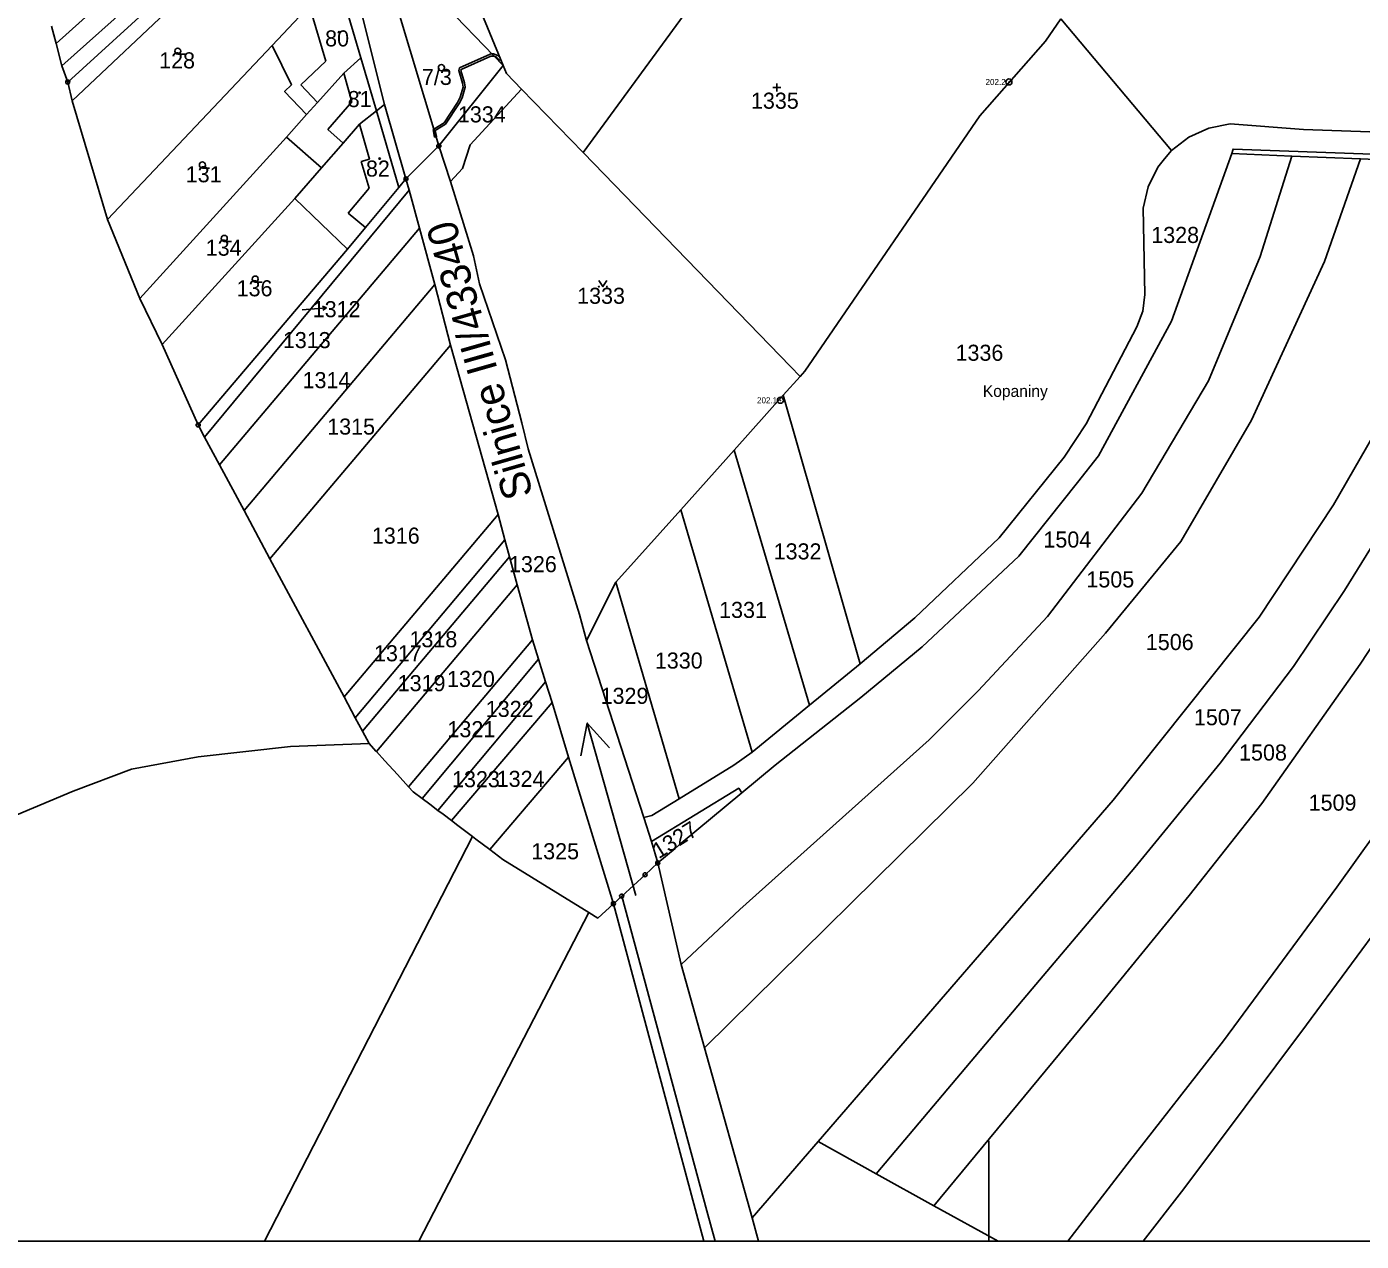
# Model space of a CAD drawing. Extents: x -564516 to -563466, y -1163913 to -1163170.
# Drawn here: x -564230.8 to -563898.7, y -1163912.5 to -1163610.3 of the extents above; entities that cross this region are included whole.
import ezdxf

# ---------------------------------------------------------------- set-up
doc = ezdxf.new("R2010")
doc.units = 0
for name, color, linetype in [('_parcely', 7, 'Continuous'), ('_parcely přehledka', 7, 'Continuous'), ('_ZOV', 7, 'Continuous'), ('Hranice parcel', 7, 'Continuous'), ('Obvod PU', 7, 'Continuous'), ('Parcelní čísla', 7, 'Continuous'), ('Pop  PČ popisy', 7, 'Continuous'), ('Vnitřní kresba', 7, 'Continuous'), ('Věcná břemena k části', 7, 'Continuous'), ('Značky bodu BP', 7, 'Continuous'), ('Značky budov', 7, 'Continuous'), ('Značky kultur', 7, 'Continuous')]:
    doc.layers.add(name, color=color, linetype=linetype)

msp = doc.modelspace()

# ---------------------------------------------------------------- linework, layer by layer
at = {"layer": '_parcely'}
msp.add_line((-563991.35, -1163912.53), (-563991.35, -1163887.53), dxfattribs=at)
at = {"layer": '_parcely přehledka'}
msp.add_lwpolyline([(-564516.35, -1163170.03), (-564516.35, -1163912.53), (-563466.35, -1163912.53), (-563466.35, -1163170.03)], dxfattribs=at)
at = {"layer": '_ZOV'}
msp.add_line((-564079.2, -1163826.53), (-564091.29, -1163783.59), dxfattribs=at)
msp.add_lwpolyline([(-564092.86, -1163791.75), (-564091.29, -1163783.59), (-564085.7, -1163789.74)], dxfattribs=at)
at = {"layer": 'Hranice parcel'}
for p, q in [((-564223.46, -1163614.55), (-564168.46, -1163564.89)), ((-564222.05, -1163620.11), (-564164.82, -1163568.62)), ((-564220.56, -1163624.11), (-564162.36, -1163571.14)), ((-564219.45, -1163628.81), (-564176.54, -1163588.25)), ((-564141.45, -1163589.58), (-564112.22, -1163619.96)), ((-564147.6, -1163618.07), (-564153.46, -1163598.26)), ((-564092.3, -1163641.63), (-564063.05, -1163601.67)), ((-564224.59, -1163610.2), (-564223.46, -1163614.55)), ((-564162.89, -1163607.78), (-564169.68, -1163615)), ((-563945.88, -1163641.11), (-563973.39, -1163608.38)), ((-564223.46, -1163614.55), (-564222.05, -1163620.11)), ((-564210.67, -1163658.27), (-564169.68, -1163615)), ((-564222.05, -1163620.11), (-564220.56, -1163624.11)), ((-564143.7, -1163631.27), (-564147.6, -1163618.07)), ((-564128.21, -1163640.02), (-564112.22, -1163619.96)), ((-564220.56, -1163624.11), (-564219.45, -1163628.81)), ((-564107.61, -1163625.85), (-564092.3, -1163641.63)), ((-564219.45, -1163628.81), (-564210.67, -1163658.27)), ((-564141.75, -1163629.73), (-564143.7, -1163631.27)), ((-564136.4, -1163648.2), (-564141.75, -1163629.73)), ((-564161.12, -1163632.21), (-564166.15, -1163637.81)), ((-564202.62, -1163678), (-564166.15, -1163637.81)), ((-564166.15, -1163637.81), (-564157.42, -1163645.45)), ((-564136.4, -1163648.2), (-564128.21, -1163640.02)), ((-564128.21, -1163640.02), (-564125.28, -1163648.88)), ((-563915.93, -1163642.54), (-563930.91, -1163641.92)), ((-563898.88, -1163643.25), (-563915.93, -1163642.54)), ((-563866.43, -1163644.59), (-563898.88, -1163643.25)), ((-564157.42, -1163645.45), (-564164.08, -1163653.05)), ((-564135.56, -1163651.03), (-564136.4, -1163648.2)), ((-564197.05, -1163689.43), (-564164.08, -1163653.05)), ((-564186.49, -1163712.43), (-564135.56, -1163651.03)), ((-564164.08, -1163653.05), (-564150.92, -1163665.7)), ((-564133.04, -1163660.47), (-564135.56, -1163651.03)), ((-564210.67, -1163658.27), (-564202.62, -1163678)), ((-564182.77, -1163719.37), (-564133.04, -1163660.47)), ((-564129.24, -1163674.51), (-564133.04, -1163660.47)), ((-564188.1, -1163709.43), (-564150.92, -1163665.7)), ((-564176.67, -1163730.73), (-564129.24, -1163674.51)), ((-564125.31, -1163689.57), (-564129.24, -1163674.51)), ((-564202.62, -1163678), (-564197.05, -1163689.43)), ((-564197.05, -1163689.43), (-564188.1, -1163709.43)), ((-564170.24, -1163742.74), (-564125.31, -1163689.57)), ((-564113.48, -1163731.73), (-564125.31, -1163689.57)), ((-564042.49, -1163702.03), (-564038.32, -1163697.37)), ((-564054.69, -1163715.66), (-564042.49, -1163702.03)), ((-564023.36, -1163768.85), (-564042.49, -1163702.03)), ((-564188.1, -1163709.43), (-564186.49, -1163712.43)), ((-564186.49, -1163712.43), (-564182.77, -1163719.37)), ((-564068.02, -1163730.56), (-564054.69, -1163715.66)), ((-564054.69, -1163715.66), (-564035.96, -1163779.13)), ((-564182.77, -1163719.37), (-564176.67, -1163730.73)), ((-564176.67, -1163730.73), (-564170.24, -1163742.74)), ((-564151.79, -1163777.11), (-564113.48, -1163731.73)), ((-564111.75, -1163738.01), (-564113.48, -1163731.73)), ((-564084.13, -1163748.56), (-564068.02, -1163730.56)), ((-564050.26, -1163790.8), (-564068.02, -1163730.56)), ((-564149.04, -1163782.26), (-564111.75, -1163738.01)), ((-564110.59, -1163742.26), (-564111.75, -1163738.01)), ((-564170.24, -1163742.74), (-564151.79, -1163777.11)), ((-564110.59, -1163742.26), (-564147.22, -1163785.64)), ((-564108.68, -1163749.18), (-564110.59, -1163742.26)), ((-564143.75, -1163790.7), (-564108.68, -1163749.18)), ((-564104.87, -1163762.87), (-564108.68, -1163749.18)), ((-564091.46, -1163763.02), (-564084.13, -1163748.56)), ((-564068.41, -1163802.44), (-564084.13, -1163748.56)), ((-564135.73, -1163799.43), (-564104.87, -1163762.87)), ((-564103.38, -1163767.72), (-564104.87, -1163762.87)), ((-564091.46, -1163763.02), (-564077.18, -1163807.12)), ((-564132.34, -1163802.38), (-564103.38, -1163767.72)), ((-564101.66, -1163773.32), (-564103.38, -1163767.72)), ((-564035.96, -1163779.13), (-564023.36, -1163768.85)), ((-564128.43, -1163805.33), (-564101.66, -1163773.32)), ((-564100.04, -1163778.49), (-564101.66, -1163773.32)), ((-564151.79, -1163777.11), (-564149.04, -1163782.26)), ((-564125.08, -1163807.86), (-564100.04, -1163778.49)), ((-564095.92, -1163792.07), (-564100.04, -1163778.49)), ((-564050.26, -1163790.8), (-564035.96, -1163779.13)), ((-564149.04, -1163782.26), (-564147.22, -1163785.64)), ((-564147.22, -1163785.64), (-564145.57, -1163788.72)), ((-564115.55, -1163815.06), (-564095.92, -1163792.07)), ((-564084.77, -1163828.54), (-564095.92, -1163792.07)), ((-564077.18, -1163807.12), (-564075.32, -1163813.06)), ((-564075.32, -1163813.06), (-564073.75, -1163818.41)), ((-564067.92, -1163843.63), (-564073.75, -1163818.41)), ((-564062.09, -1163864.39), (-564067.92, -1163843.63)), ((-564050.26, -1163906.68), (-564062.09, -1163864.39)), ((-564050.26, -1163906.68), (-564033.85, -1163887.71)), ((-564033.85, -1163887.71), (-564019.41, -1163895.71)), ((-564019.41, -1163895.71), (-564005.03, -1163903.67)), ((-564005.03, -1163903.67), (-563989.02, -1163912.53))]:
    msp.add_line(p, q, dxfattribs=at)
for points in [[(-564141.75, -1163629.73), (-564147.11, -1163608.19), (-564150.44, -1163590.7), (-564149.91, -1163571.99), (-564143.77, -1163544.97)], [(-564112.22, -1163619.96), (-564129.19, -1163578.66), (-564125.43, -1163565.71)], [(-564141.45, -1163589.58), (-564138.93, -1163604.36), (-564128.21, -1163640.02)], [(-564038.32, -1163697.37), (-564037.15, -1163696.07), (-563993.61, -1163632.54), (-563977.25, -1163613.92), (-563973.39, -1163608.38)], [(-564169.68, -1163615), (-564164.9, -1163624.84), (-564166.58, -1163626.42), (-564161.12, -1163632.21)], [(-564161.12, -1163632.21), (-564158.44, -1163629.22), (-564151.87, -1163621.91), (-564147.6, -1163618.07)], [(-564112.22, -1163619.96), (-564111.4, -1163621.95), (-564107.61, -1163625.85)], [(-564125.28, -1163648.88), (-564122.35, -1163645.58), (-564120.45, -1163639.74), (-564107.61, -1163625.85)], [(-564157.42, -1163645.45), (-564152.02, -1163639.28), (-564147.94, -1163634.62), (-564143.7, -1163631.27)], [(-563945.88, -1163641.11), (-563941.57, -1163637.81), (-563936.63, -1163635.58), (-563931.3, -1163634.54), (-563913.06, -1163635.92), (-563861.14, -1163637.78)], [(-564092.3, -1163641.63), (-564040.72, -1163694.91), (-564038.32, -1163697.37)], [(-564067.92, -1163843.63), (-564053.32, -1163830), (-564006.23, -1163787.74), (-563993.99, -1163775.6), (-563976.74, -1163757.12), (-563953.25, -1163726.38), (-563936.65, -1163698.43), (-563923.86, -1163667.53), (-563915.93, -1163642.54)], [(-564062.09, -1163864.39), (-563995.33, -1163798.54), (-563962.27, -1163761.24), (-563943.57, -1163738.41), (-563925.96, -1163708.23), (-563907.83, -1163668.76), (-563898.88, -1163643.25)], [(-564023.36, -1163768.85), (-564009.73, -1163757.43), (-563988.8, -1163737.54), (-563972.63, -1163717.42), (-563967.15, -1163709.12), (-563954.55, -1163685.04), (-563953.03, -1163681.15), (-563952.52, -1163676.96), (-563952.92, -1163655.47), (-563951.71, -1163650.18), (-563949.32, -1163645.31), (-563947.61, -1163643.22), (-563945.88, -1163641.11)], [(-564033.85, -1163887.71), (-563960.37, -1163802.77), (-563924.09, -1163757.23), (-563905.61, -1163729.28), (-563893.92, -1163709.01), (-563880, -1163679.45), (-563866.43, -1163644.59)], [(-564019.41, -1163895.71), (-563980.6, -1163849.7), (-563954.99, -1163819.51), (-563933.77, -1163793.6), (-563915.51, -1163769.54), (-563902.82, -1163750.6), (-563880.21, -1163714.08), (-563865.64, -1163681.81), (-563852.28, -1163645.65)], [(-564005.03, -1163903.67), (-563965.09, -1163855.39), (-563941.49, -1163826.5), (-563923.42, -1163803.62), (-563898.92, -1163768.98), (-563879.88, -1163739.93), (-563867.29, -1163716.65), (-563853.12, -1163688.16), (-563837.56, -1163646.83)], [(-564150.92, -1163665.7), (-564146.44, -1163660.3), (-564138.18, -1163650.34), (-564136.4, -1163648.2)], [(-564125.28, -1163648.88), (-564119.58, -1163667.35), (-564118.1, -1163674.3), (-564111.58, -1163693.21), (-564107.59, -1163708.92), (-564105.94, -1163715.39), (-564093.18, -1163756.62), (-564091.46, -1163763.02)], [(-563971.69, -1163912.53), (-563956.92, -1163893.35), (-563932.93, -1163862.62), (-563904.78, -1163824.4), (-563885.89, -1163798.15), (-563869.34, -1163772.9), (-563860.8, -1163759.16), (-563843.13, -1163727.45), (-563830.48, -1163702.96), (-563823.28, -1163687.14), (-563818.58, -1163675.31), (-563810.46, -1163651.3)], [(-563952.94, -1163912.53), (-563942.84, -1163899.5), (-563912.32, -1163858.67), (-563872.16, -1163804.24), (-563858.94, -1163783.59), (-563847.66, -1163765.02), (-563838.38, -1163748.17), (-563818.3, -1163711.53), (-563805.22, -1163681.25), (-563795.8, -1163653.08)], [(-564068.41, -1163802.44), (-564054.76, -1163794.08), (-564050.26, -1163790.8)], [(-564052.83, -1163800.98), (-564053.56, -1163799.83), (-564075.32, -1163813.06)], [(-564077.18, -1163807.12), (-564075.21, -1163806.57), (-564068.41, -1163802.44)], [(-564171.55, -1163912.53), (-564119.83, -1163811.83)], [(-564084.77, -1163828.54), (-564064.12, -1163905.73), (-564062.23, -1163912.53)], [(-564082.71, -1163826.65), (-564061.52, -1163904.92), (-564059.43, -1163912.53)], [(-564090.91, -1163830.72), (-564133.16, -1163912.53)], [(-564048.67, -1163912.53), (-564050.26, -1163906.68)]]:
    msp.add_lwpolyline(points, dxfattribs=at)
at = {"layer": 'Obvod PU'}
msp.add_line((-564082.71, -1163826.65), (-564084.77, -1163828.54), dxfattribs=at)
msp.add_line((-564082.71, -1163826.65), (-564084.77, -1163828.54), dxfattribs=at)
for points in [[(-563930.91, -1163641.92), (-563945.92, -1163683.61), (-563964.08, -1163717.1), (-563969.31, -1163723.74), (-563983.9, -1163742.07), (-564007.92, -1163764.64), (-564023.16, -1163777.23), (-564044.53, -1163794.09), (-564052.83, -1163800.98)], [(-563930.91, -1163641.92), (-563945.92, -1163683.61), (-563964.08, -1163717.1), (-563969.31, -1163723.74), (-563983.9, -1163742.07), (-564007.92, -1163764.64), (-564023.16, -1163777.23), (-564044.53, -1163794.09), (-564052.83, -1163800.98)], [(-563863.67, -1163643.2), (-563930.57, -1163640.78), (-563930.91, -1163641.92)], [(-563863.67, -1163643.2), (-563930.57, -1163640.78), (-563930.91, -1163641.92)], [(-564145.57, -1163788.72), (-564165.13, -1163789.46), (-564188.06, -1163792), (-564204.66, -1163795.09), (-564219.21, -1163800.53), (-564275.9, -1163824.32), (-564309.77, -1163843.83), (-564359.7, -1163877.05), (-564371.94, -1163888.45), (-564374.47, -1163874.66), (-564375.88, -1163841.01), (-564379.57, -1163838.23)], [(-564145.57, -1163788.72), (-564165.13, -1163789.46), (-564188.06, -1163792), (-564204.66, -1163795.09), (-564219.21, -1163800.53), (-564275.9, -1163824.32), (-564309.77, -1163843.83), (-564359.7, -1163877.05), (-564371.94, -1163888.45), (-564374.47, -1163874.66), (-564375.88, -1163841.01), (-564379.57, -1163838.23)], [(-564143.75, -1163790.7), (-564143.87, -1163790.57), (-564145.57, -1163788.72)], [(-564143.75, -1163790.7), (-564143.87, -1163790.57), (-564145.57, -1163788.72)], [(-564135.73, -1163799.43), (-564138.49, -1163796.43), (-564141.64, -1163793), (-564143.75, -1163790.7)], [(-564135.73, -1163799.43), (-564138.49, -1163796.43), (-564141.64, -1163793), (-564143.75, -1163790.7)], [(-564132.34, -1163802.38), (-564134.59, -1163800.68), (-564135.73, -1163799.43)], [(-564132.34, -1163802.38), (-564134.59, -1163800.68), (-564135.73, -1163799.43)], [(-564128.43, -1163805.33), (-564130.46, -1163803.8), (-564132.34, -1163802.38)], [(-564128.43, -1163805.33), (-564130.46, -1163803.8), (-564132.34, -1163802.38)], [(-564052.83, -1163800.98), (-564067.88, -1163813.47), (-564069.41, -1163814.81), (-564073.75, -1163818.41)], [(-564052.83, -1163800.98), (-564067.88, -1163813.47), (-564069.41, -1163814.81), (-564073.75, -1163818.41)], [(-564125.08, -1163807.86), (-564127.17, -1163806.28), (-564128.43, -1163805.33)], [(-564125.08, -1163807.86), (-564127.17, -1163806.28), (-564128.43, -1163805.33)], [(-564119.83, -1163811.83), (-564123.49, -1163809.06), (-564125.08, -1163807.86)], [(-564119.83, -1163811.83), (-564123.49, -1163809.06), (-564125.08, -1163807.86)], [(-564115.55, -1163815.06), (-564119, -1163812.46), (-564119.83, -1163811.83)], [(-564115.55, -1163815.06), (-564119, -1163812.46), (-564119.83, -1163811.83)], [(-564090.91, -1163830.72), (-564112.29, -1163817.52), (-564115.55, -1163815.06)], [(-564090.91, -1163830.72), (-564112.29, -1163817.52), (-564115.55, -1163815.06)], [(-564073.75, -1163818.41), (-564076.9, -1163821.34), (-564082.71, -1163826.65)], [(-564073.75, -1163818.41), (-564076.9, -1163821.34), (-564082.71, -1163826.65)], [(-564084.77, -1163828.54), (-564088.67, -1163832.11), (-564090.91, -1163830.72)], [(-564084.77, -1163828.54), (-564088.67, -1163832.11), (-564090.91, -1163830.72)]]:
    msp.add_lwpolyline(points, dxfattribs=at)
at = {"layer": 'Pop  PČ popisy'}
for p, q in [((-564159.11, -1163680.51), (-564156.12, -1163680.25)), ((-564156.12, -1163680.25), (-564157.16, -1163679.84)), ((-564156.12, -1163680.25), (-564157.07, -1163680.84)), ((-564162.18, -1163680.77), (-564159.11, -1163680.51))]:
    msp.add_line(p, q, dxfattribs=at)
at = {"layer": 'Vnitřní kresba'}
for p, q in [((-564160.37, -1163605.23), (-564156.31, -1163618.94)), ((-564156.31, -1163618.94), (-564162.57, -1163624.84)), ((-564149.84, -1163629.05), (-564151.87, -1163621.91)), ((-564158.44, -1163629.22), (-564162.57, -1163624.84)), ((-564149.84, -1163629.05), (-564155.86, -1163635.92)), ((-564138.18, -1163650.34), (-564143.7, -1163631.27)), ((-564155.86, -1163635.92), (-564152.02, -1163639.28)), ((-564145.43, -1163643.26), (-564147.94, -1163634.62)), ((-564145.43, -1163643.26), (-564147.5, -1163643.86)), ((-564147.5, -1163643.86), (-564145.58, -1163650.49)), ((-564150.75, -1163656.72), (-564145.58, -1163650.49)), ((-564150.75, -1163656.72), (-564146.44, -1163660.3))]:
    msp.add_line(p, q, dxfattribs=at)
at = {"layer": 'Věcná břemena k části'}
msp.add_lwpolyline([(-564129.09, -1163636.18), (-564126.56, -1163634.59), (-564123.17, -1163629.45), (-564122.4, -1163628.02), (-564121.66, -1163625.41), (-564121.8, -1163624.29), (-564122.71, -1163621.24), (-564122.63, -1163620.95), (-564115.3, -1163617.69), (-564114.43, -1163617.66), (-564113.85, -1163617.89), (-564113.13, -1163618.68), (-564112.79, -1163618.58), (-564113.13, -1163617.74), (-564113.27, -1163617.78), (-564113.55, -1163617.47), (-564114.58, -1163617.06), (-564114.95, -1163617.12), (-564115.44, -1163617.21), (-564123.05, -1163620.59), (-564123.23, -1163621.24), (-564122.3, -1163624.39), (-564122.16, -1163625.37), (-564122.86, -1163627.84), (-564123.59, -1163629.19), (-564126.92, -1163634.23), (-564129.47, -1163635.83), (-564129.65, -1163635.94), (-564129.26, -1163637.8), (-564128.9, -1163637.72), (-564128.77, -1163637.69)], close=True, dxfattribs=at)
at = {"layer": 'Značky bodu BP'}
for centre, radius in [((-564220.56, -1163624.11), 0.5), ((-563986.34, -1163624.09), 0.75), ((-564220.56, -1163624.11), 0.0303), ((-563986.34, -1163624.09), 0.03), ((-564128.21, -1163640.02), 0.5), ((-564128.21, -1163640.02), 0.0303), ((-564136.4, -1163648.2), 0.5), ((-564136.4, -1163648.2), 0.0303), ((-564043.21, -1163703.28), 0.75), ((-564043.21, -1163703.28), 0.03), ((-564188.1, -1163709.43), 0.5), ((-564188.1, -1163709.43), 0.0303), ((-564073.75, -1163818.41), 0.5), ((-564073.75, -1163818.41), 0.0303), ((-564076.9, -1163821.34), 0.5), ((-564076.9, -1163821.34), 0.0303), ((-564082.71, -1163826.65), 0.5), ((-564082.71, -1163826.65), 0.0303), ((-564084.77, -1163828.54), 0.5), ((-564084.77, -1163828.54), 0.0303)]:
    msp.add_circle(centre, radius, dxfattribs=at)
at = {"layer": 'Značky budov'}
for centre in [(-564153.05, -1163611.7), (-564147.94, -1163626.79), (-564142.94, -1163643.16)]:
    msp.add_circle(centre, 0.175, dxfattribs=at)
at = {"layer": 'Značky kultur'}
for p, q in [((-564193.17, -1163617.17), (-564191.42, -1163617.17)), ((-564127.56, -1163621.28), (-564125.81, -1163621.28)), ((-564043.13, -1163625.48), (-564045.13, -1163625.48)), ((-564044.13, -1163626.48), (-564044.13, -1163624.48)), ((-564187.04, -1163645.5), (-564185.29, -1163645.5)), ((-564181.59, -1163663.77), (-564179.84, -1163663.77)), ((-564173.9, -1163673.87), (-564172.15, -1163673.87))]:
    msp.add_line(p, q, dxfattribs=at)
msp.add_lwpolyline([(-564088.37, -1163673.51), (-564087.37, -1163675.01), (-564086.37, -1163673.51)], dxfattribs=at)
for centre, radius in [((-564193.17, -1163616.42), 0.75), ((-564127.56, -1163620.53), 0.75), ((-564187.04, -1163644.75), 0.75), ((-564181.59, -1163663.02), 0.75), ((-564173.9, -1163673.12), 0.75), ((-564088.37, -1163675.01), 0.1), ((-564086.37, -1163675.01), 0.1)]:
    msp.add_circle(centre, radius, dxfattribs=at)

# ---------------------------------------------------------------- texts
at = {"layer": '_ZOV'}
msp.add_text('Silnice III/43340', height=7.5, rotation=105.9051, dxfattribs=at).set_placement((-564104.68, -1163726.69))
at = {"layer": 'Parcelní čísla'}
for s, p in [('80', (-564156.5, -1163615.25)), ('128', (-564197.8, -1163620.72)), ('7/3', (-564132.41, -1163624.83)), ('81', (-564150.88, -1163630.34)), ('1335', (-564050.54, -1163630.75)), ('1334', (-564123.46, -1163634.15)), ('82', (-564146.35, -1163647.63)), ('131', (-564191.19, -1163649.05)), ('1328', (-563950.92, -1163664.15)), ('134', (-564186.22, -1163667.32)), ('136', (-564178.53, -1163677.42)), ('1333', (-564093.79, -1163679.28)), ('1312', (-564159.59, -1163682.62)), ('1313', (-564167.02, -1163690.31)), ('1336', (-563999.63, -1163693.46)), ('1314', (-564162.12, -1163700.28)), ('1315', (-564155.98, -1163711.83)), ('1316', (-564144.87, -1163738.96)), ('1504', (-563977.76, -1163739.93)), ('1332', (-564044.89, -1163742.88)), ('1326', (-564110.75, -1163746.06)), ('1505', (-563967.06, -1163749.85)), ('1331', (-564058.46, -1163757.44)), ('1318', (-564135.52, -1163764.74)), ('1506', (-563952.27, -1163765.43)), ('1317', (-564144.34, -1163768.23)), ('1330', (-564074.45, -1163770.04)), ('1319', (-564138.45, -1163775.66)), ('1320', (-564126.17, -1163774.61)), ('1329', (-564087.95, -1163778.82)), ('1322', (-564116.53, -1163782.07)), ('1507', (-563940.31, -1163784.14)), ('1321', (-564126.07, -1163787.12)), ('1508', (-563929.07, -1163792.92)), ('1323', (-564124.93, -1163799.56)), ('1324', (-564113.81, -1163799.48)), ('1509', (-563911.76, -1163805.39)), ('1325', (-564105.21, -1163817.49))]:
    msp.add_text(s, height=4, dxfattribs=at).set_placement(p)
msp.add_text('1327', height=4, rotation=32, dxfattribs=at).set_placement((-564073.49, -1163817.5))
at = {"layer": 'Pop  PČ popisy'}
msp.add_text('Kopaniny', height=2.9, dxfattribs=at).set_placement((-563992.84, -1163702.44))
at = {"layer": 'Značky bodu BP'}
for s, p in [('202.2', (-563992.16, -1163624.84)), ('202.1', (-564049.03, -1163704.03))]:
    msp.add_text(s, height=1.5, dxfattribs=at).set_placement(p)

doc.saveas('drawing.dxf')
